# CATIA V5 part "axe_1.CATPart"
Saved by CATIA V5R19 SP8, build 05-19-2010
Part number: axe_1
Bounding box of the stored display mesh (mm): x 0 to 330, y -4.999 to 4.999, z -4.999 to 4.999
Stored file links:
  C:\Users\ThinkMotion\Desktop\EU_thinkMotion\iao\IAO_MMS_Groupe3\avercruysse\IAO_vercruysse\IAO_vercruysse\axe_1.CATPart
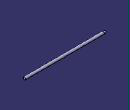
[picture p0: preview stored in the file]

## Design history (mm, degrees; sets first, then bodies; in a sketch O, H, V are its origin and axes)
Body1 (main body)
  Sketch1 on xy-plane, origin (0, 0, 0), H (1, 0, 0), V (0, 1, 0)
    axis line L1 (130.1635, 0) -> (-86.6706, 0)
    point P1 (130.1635, 0)
    line L2 (0, 0) -> (0, 4)
    line L3 (0, 4) -> (10, 4)
    line L4 (10, 4) -> (10, 5)
    line L5 (10, 5) -> (330, 5)
    line L6 (330, 5) -> (330, 0)
    point P7 (330, 0)
    length L2 = 4
    length L3 = 10
    distance L5 L1 = 5
    length L5 = 320
    coincidence: P1 H, P7 L1
    horizontal: L1 H, L5 H, L3 H
    vertical: L2 V, L4 V, L6 V
  Shaft1: profile Sketch1, axis Sketch1.L1, angle 360
  Chamfer1: length 1, angle 45, on edge [face of Shaft1 from Sketch1.L3 | face of Shaft1 from Sketch1.L2]
  Thread1: "M8", diameter 8, depth 10, pitch 1.25, on face of Shaft1 from Sketch1.L3, from face of Shaft1 from Sketch1.L2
